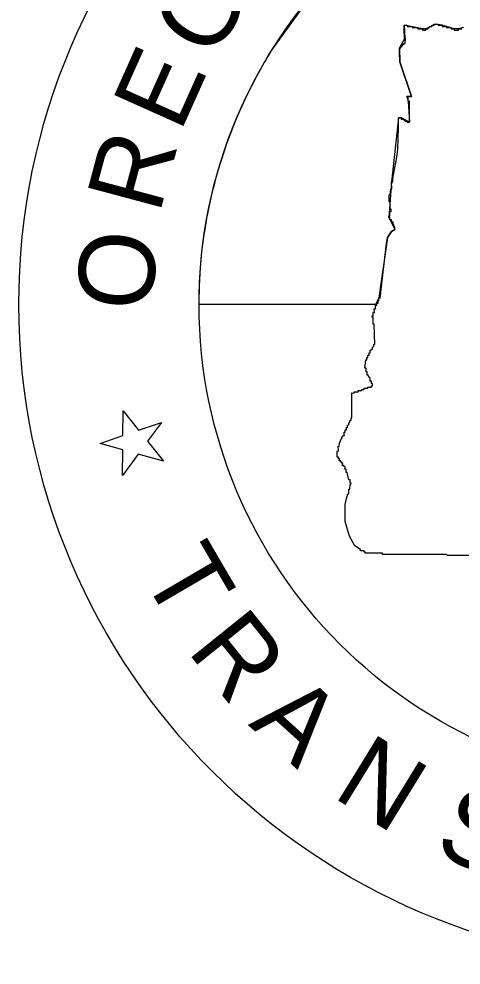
# Model space of a CAD drawing. Extents: x 0 to 1.42, y 0 to 0.92.
# Drawn here: x 1.32918 to 1.34592, y 0.07917 to 0.11497 of the extents above; entities that cross this region are included whole.
import ezdxf

# ---------------------------------------------------------------- set-up
doc = ezdxf.new("R2010")
doc.units = 0
doc.layers.add('P_ODOT_PLAN_TBlock', color=7, linetype='Continuous')

msp = doc.modelspace()

# ---------------------------------------------------------------- linework, layer by layer
at = {"layer": 'P_ODOT_PLAN_TBlock'}
for points in [[(1.34601, 0.114639), (1.34582, 0.114595), (1.345651, 0.114595), (1.345205, 0.114729), (1.344971, 0.114774), (1.34459, 0.114595), (1.344454, 0.114595), (1.343766, 0.114729), (1.343794, 0.114236), (1.343591, 0.113875), (1.343598, 0.11334), (1.344047, 0.112031), (1.343868, 0.112035), (1.343914, 0.111856), (1.343966, 0.111064), (1.343658, 0.111226), (1.343548, 0.111227), (1.343287, 0.108804), (1.343183, 0.107457), (1.343408, 0.107005), (1.343285, 0.10692), (1.343137, 0.106699), (1.342806, 0.104413), (1.342678, 0.104167), (1.336005, 0.104167), (1.336005, 0.104228), (1.336005, 0.104343), (1.336015, 0.104787), (1.336024, 0.104997), (1.336056, 0.105568), (1.33611, 0.106147), (1.336118, 0.106258), (1.336198, 0.106813), (1.336205, 0.106859), (1.336205, 0.106859), (1.336206, 0.106864), (1.336216, 0.106933), (1.336228, 0.107007), (1.336252, 0.107155), (1.33627, 0.107259), (1.336299, 0.107424), (1.33633, 0.10759), (1.336371, 0.107797), (1.33642, 0.108028), (1.336471, 0.108259), (1.336545, 0.108568), (1.336593, 0.108754), (1.336661, 0.109008), (1.336728, 0.109241), (1.33677, 0.109386), (1.33677, 0.109387), (1.336773, 0.109395), (1.33678, 0.10942), (1.336845, 0.10963), (1.336947, 0.109943), (1.337067, 0.110291), (1.337198, 0.110642), (1.337294, 0.11089), (1.337352, 0.111034), (1.337361, 0.111058), (1.337369, 0.111076), (1.337375, 0.111091), (1.337379, 0.1111), (1.337379, 0.111101), (1.337382, 0.111107), (1.337394, 0.111138), (1.337422, 0.111202), (1.337555, 0.111513), (1.337628, 0.111675), (1.337669, 0.111763), (1.337693, 0.111816), (1.337782, 0.112006), (1.3379, 0.112249), (1.338064, 0.112571), (1.338214, 0.112852), (1.338299, 0.113007), (1.338328, 0.113058), (1.338469, 0.113306), (1.338523, 0.113398), (1.338583, 0.113499), (1.338662, 0.11363), (1.338734, 0.113747), (1.338815, 0.113877), (1.340143, 0.115714)], [(1.346483, 0.094664), (1.345402, 0.094662), (1.345362, 0.094701), (1.342941, 0.094708), (1.34294, 0.094757), (1.342292, 0.094755), (1.342292, 0.094802), (1.342246, 0.094796), (1.342248, 0.094842), (1.342118, 0.094844), (1.342118, 0.094889), (1.341899, 0.095027), (1.341701, 0.095402), (1.341532, 0.095949), (1.341528, 0.096322), (1.341536, 0.096591), (1.341582, 0.096819), (1.341629, 0.096999), (1.341665, 0.096996), (1.341672, 0.097178), (1.341706, 0.097173), (1.341716, 0.097357), (1.34175, 0.097358), (1.341763, 0.0974), (1.341715, 0.0974), (1.341718, 0.097527), (1.341667, 0.097534), (1.341612, 0.097805), (1.341565, 0.097802), (1.341564, 0.097936), (1.341517, 0.097935), (1.341526, 0.098023), (1.341478, 0.098027), (1.34149, 0.098075), (1.341417, 0.098074), (1.341446, 0.098165), (1.341402, 0.098162), (1.3414, 0.098208), (1.341354, 0.098202), (1.341351, 0.098265), (1.341309, 0.098251), (1.341316, 0.09834), (1.341268, 0.098341), (1.341276, 0.098385), (1.341229, 0.098386), (1.341227, 0.098618), (1.341274, 0.098622), (1.341266, 0.0988), (1.341306, 0.098791), (1.341313, 0.098921), (1.341448, 0.099202), (1.341495, 0.099199), (1.341493, 0.099331), (1.34153, 0.099336), (1.341535, 0.099423), (1.34158, 0.099419), (1.341585, 0.099516), (1.341624, 0.099512), (1.341624, 0.099603), (1.341668, 0.099605), (1.341669, 0.099691), (1.341714, 0.099698), (1.341714, 0.099779), (1.341758, 0.099788), (1.341758, 0.09987), (1.34178, 0.099877), (1.341783, 0.10082), (1.341873, 0.100811), (1.341867, 0.100863), (1.342032, 0.100862), (1.342029, 0.100904), (1.342163, 0.100907), (1.342163, 0.100948), (1.342254, 0.100952), (1.342254, 0.100997), (1.342389, 0.100996), (1.342386, 0.10104), (1.342522, 0.101038), (1.342523, 0.101083), (1.342568, 0.101082), (1.342565, 0.101169), (1.342524, 0.101172), (1.342525, 0.10126), (1.342479, 0.101262), (1.342476, 0.101394), (1.342437, 0.101397), (1.342406, 0.101484), (1.342364, 0.101487), (1.342365, 0.10162), (1.34232, 0.10162), (1.342322, 0.101754), (1.342277, 0.101753), (1.342311, 0.102069), (1.342352, 0.102071), (1.342351, 0.10216), (1.342394, 0.102159), (1.342386, 0.102251), (1.342436, 0.102249), (1.342435, 0.102339), (1.342478, 0.102338), (1.342478, 0.10243), (1.34252, 0.102432), (1.342523, 0.102474), (1.342566, 0.102473), (1.342563, 0.102563), (1.342614, 0.102568), (1.342613, 0.102656), (1.34266, 0.102656), (1.342626, 0.103414), (1.342586, 0.103417), (1.342594, 0.103686), (1.342548, 0.103681), (1.342549, 0.103732), (1.342591, 0.103724), (1.342596, 0.103865), (1.342638, 0.103864), (1.342629, 0.104), (1.342679, 0.104004), (1.342678, 0.10414), (1.342726, 0.104134), (1.342721, 0.104219), (1.342784, 0.104214), (1.342768, 0.104315), (1.342808, 0.104306), (1.342806, 0.104413), (1.342858, 0.104399), (1.343102, 0.10647), (1.343137, 0.106699), (1.343285, 0.10692), (1.343408, 0.107005), (1.343414, 0.107093), (1.343381, 0.107099), (1.343379, 0.107185), (1.343341, 0.107184), (1.343343, 0.107276), (1.343304, 0.107279), (1.343286, 0.107366), (1.343221, 0.107367), (1.343228, 0.107455), (1.343183, 0.107457), (1.343187, 0.107503), (1.343222, 0.107505), (1.343227, 0.107682), (1.343268, 0.107683), (1.343267, 0.107767), (1.343229, 0.10777), (1.343231, 0.108034), (1.343195, 0.108043), (1.343195, 0.108308), (1.343234, 0.10831), (1.343254, 0.108533), (1.343298, 0.108536), (1.343287, 0.108804), (1.343332, 0.108802), (1.343333, 0.108937), (1.343484, 0.109744), (1.343523, 0.110038), (1.343545, 0.110843), (1.343548, 0.111227), (1.343658, 0.111226), (1.343657, 0.111182), (1.343756, 0.111181), (1.343757, 0.11114), (1.343797, 0.111137), (1.343798, 0.111093), (1.343883, 0.111094), (1.34388, 0.11105), (1.343966, 0.111064), (1.343962, 0.111856), (1.343914, 0.111856), (1.343916, 0.111989), (1.343872, 0.111992), (1.343868, 0.112035), (1.344047, 0.112031), (1.343598, 0.11334), (1.34359, 0.113696), (1.343591, 0.113875), (1.343633, 0.113875), (1.343635, 0.11392), (1.343677, 0.113923), (1.343678, 0.113966), (1.343717, 0.113967), (1.343717, 0.11401), (1.343762, 0.11401), (1.343761, 0.114055), (1.343804, 0.114057), (1.343812, 0.114236), (1.343775, 0.114236), (1.343766, 0.11455), (1.343766, 0.114729), (1.343878, 0.114729), (1.343879, 0.114684), (1.344077, 0.114683), (1.344077, 0.114638), (1.344288, 0.11464), (1.344284, 0.114595), (1.344454, 0.114595), (1.344454, 0.11455), (1.34459, 0.11455), (1.34459, 0.114595), (1.344679, 0.114595), (1.344679, 0.11464), (1.344724, 0.11464), (1.344724, 0.114685), (1.344808, 0.114685), (1.344808, 0.114729), (1.344894, 0.114729), (1.344893, 0.114774), (1.345049, 0.114774), (1.34505, 0.11473), (1.345205, 0.114729), (1.345201, 0.114685), (1.345363, 0.114685), (1.345363, 0.11464), (1.345539, 0.11464), (1.34554, 0.114593), (1.345651, 0.114595), (1.345653, 0.11455), (1.345818, 0.11455), (1.34582, 0.114595), (1.345942, 0.114594)]]:
    msp.add_lwpolyline(points, dxfattribs=at)
msp.add_lwpolyline([(1.332257, 0.098903), (1.333118, 0.0992), (1.33313, 0.100135), (1.333715, 0.099405), (1.334576, 0.099702), (1.33405, 0.098987), (1.334655, 0.098232), (1.333692, 0.098502), (1.333099, 0.097697), (1.333111, 0.098664)], close=True, dxfattribs=at)
for radius in [0.025, 0.018179]:
    msp.add_circle((1.354183, 0.104167), radius, dxfattribs=at)

# ---------------------------------------------------------------- texts
for s, rotation, p in [('G', 57.374, (1.336443, 0.113347)), ('E', 65.8562, (1.335283, 0.11063)), ('R', 75.0182, (1.334495, 0.107538)), ('O', 85.5786, (1.334211, 0.103872)), ('T', 300.2744, (1.333783, 0.093968)), ('R', 308.78, (1.335516, 0.091062)), ('A', 317.942, (1.337841, 0.088257)), ('N', 328.4086, (1.341003, 0.085553)), ('S', 339.5081, (1.344833, 0.083364))]:
    msp.add_text(s, height=0.002869, rotation=rotation, dxfattribs=at).set_placement(p)

doc.saveas('drawing.dxf')
